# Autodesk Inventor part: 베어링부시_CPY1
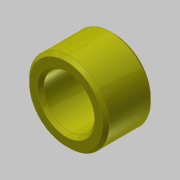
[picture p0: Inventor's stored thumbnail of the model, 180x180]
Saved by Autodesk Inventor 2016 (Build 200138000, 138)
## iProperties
Created: 2019-03
Part Number: 베어링부시_CPY1
Material: 강철, 연강
Document SubType Name: Modeling
Designer: Administrator
Density: 1 g/cm^3
Appearance: 노란색
Author: mduedu
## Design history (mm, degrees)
sketch "스케치1"
  geometry: L1 (-7.5, 12.5)-(7.5, 12.5); L2 (7.5, 12.5)-(7.5, 8); L3 (7.5, 8)-(-7.5, 8); L4 (-7.5, 8)-(-7.5, 12.5); L5 (-7.5, 0)-(7.5, 0); 3 further points
  constraints: 10 end point, 2 midpoint, 2 parallel, 2 perpendicular, 2 vertical alignment, 1 coincident, 1 horizontal
  dimensions: "d0" = 16 diameter of L3 L5; "d2" = 25 diameter of L1 L5; "d3" = 15 distance of L1.start L1.end
revolve "회전1" sketch "스케치1" stored, may be unused: angle "d4" = 90 deg
chamfer "모따기1" distance "d5" = 1; stored, may be unused: second distance "d6" = 2, angle "d7" = 45 deg
chamfer "모따기2" distance "d8" = 1; stored, may be unused: second distance "d9" = 2, angle "d10" = 45 deg
node "솔리드1"
